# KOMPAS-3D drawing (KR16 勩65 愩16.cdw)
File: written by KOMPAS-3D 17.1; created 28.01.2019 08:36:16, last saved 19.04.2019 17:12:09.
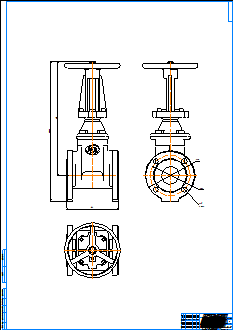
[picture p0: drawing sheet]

Sheet 1: A0, portrait

Title block, sheet 1: name: KR16 Ду65 Ру16; material: Внимание! Данный продукт является объектом авторского права ООО «Торговый Дом АДЛ». / Запрещается изменение, копирование, распространение / (в том числе путем копирования на другие сайты и ресурсы в Интернете) / или любое иное использование информации и объектов без предварительного / согласия правообладателя (ООО «Торговый Дом АДЛ»).; sheets: 1; organisation: ООО "Торговый дом АДЛ"; sheet format: A0; stored path: \\adlc.lan\data\АДЛ_ПКД\3D-модели\ADL production\Клиновые задвижки серии KR ГРАНАР\Клиновые задвижки KR16\Со штурвалом\KOMPAS 2D\KR16 Ду65.cdw

Views: Вид 1, Проекционный вид 2, Проекционный вид 3
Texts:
  user
Dimensions and other numbers on the sheet: 190; 503,5; 411; 180; 19; 4 отв.; 145; 1:1; 1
